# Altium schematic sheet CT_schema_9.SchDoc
size 277 x 170 mm
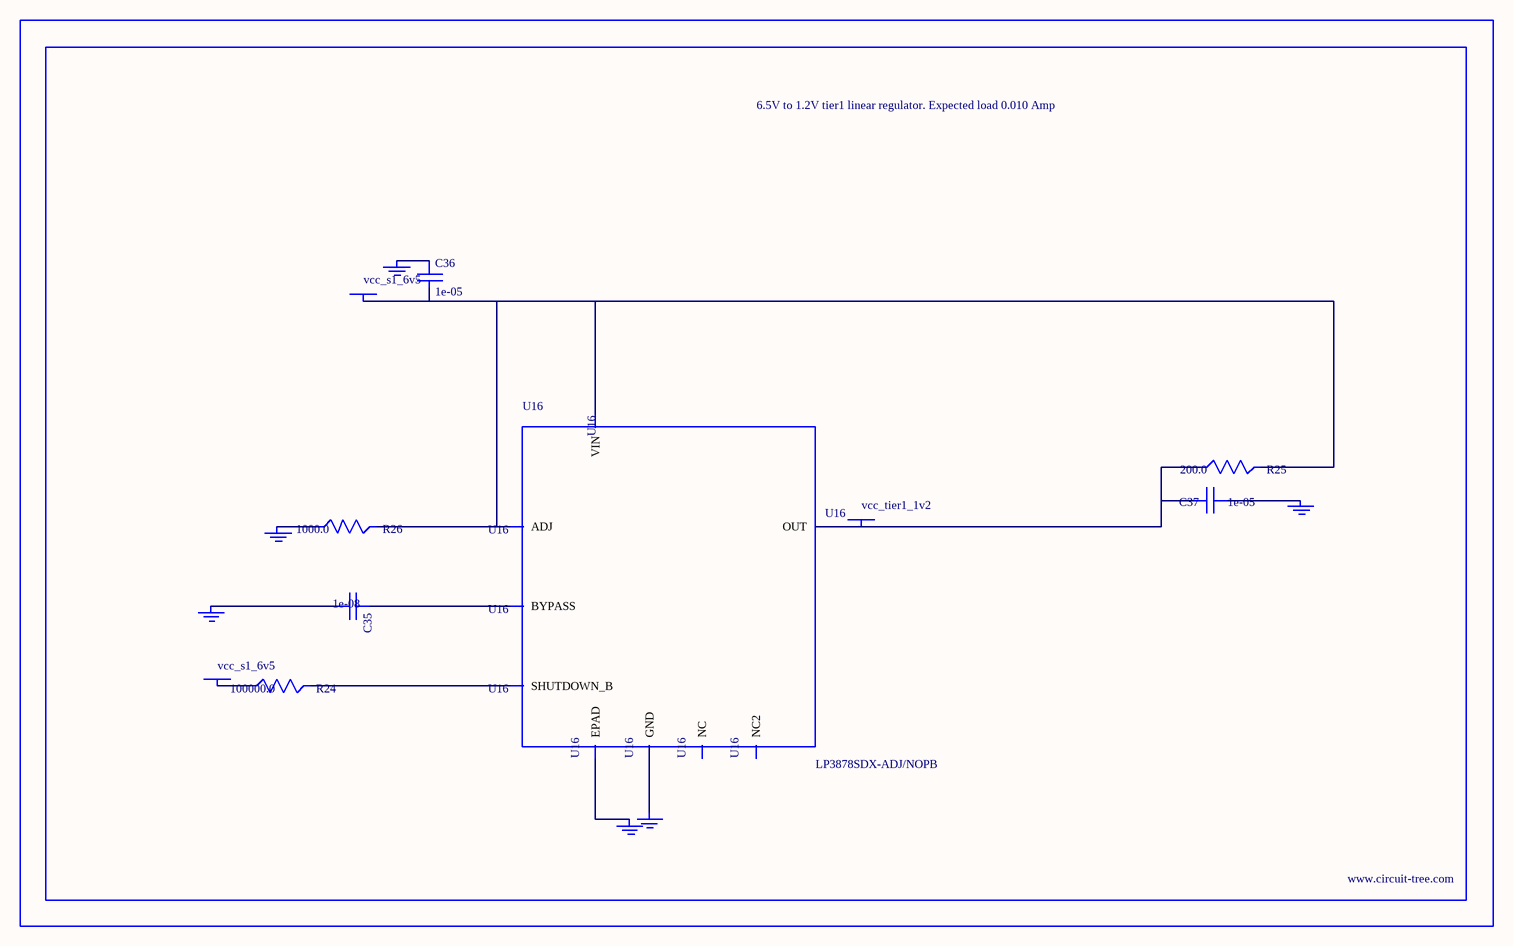
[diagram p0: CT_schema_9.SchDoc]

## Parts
BORDER8  (no value)
C35  1e-08  [C0402]
C36  1e-05  [C1206]
C37  1e-05  [C0805]
GND_INSTANCE_8_0  (no value)
GND_INSTANCE_8_1  (no value)
GND_INSTANCE_8_2  (no value)
GND_INSTANCE_8_3  (no value)
GND_INSTANCE_8_4  (no value)
GND_INSTANCE_8_5  (no value)
POWER_INSTANCE_8_0  vcc_s1_6v5
POWER_INSTANCE_8_1  vcc_s1_6v5
POWER_INSTANCE_8_2  vcc_tier1_1v2
R24  100000.0  [R0603]
R25  200.0  [R0603]
R26  1000.0  [R0603]
U16  LP3878SDX-ADJ/NOPB  [WSON-8]

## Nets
NetC35_1: C35.1 U16.1(BYPASS)
NetC35_2: C35.2 GND_INSTANCE_8_0.0(GND)
NetC36_1: C36.1 GND_INSTANCE_8_1.0(GND)
NetC36_2: C36.2 POWER_INSTANCE_8_0.0(PWR) R25.2 R26.2 U16.4(VIN) U16.6(ADJ)
NetC37_1: C37.1 GND_INSTANCE_8_2.0(GND)
NetC37_2: C37.2 POWER_INSTANCE_8_2.0(PWR) R25.1 U16.5(OUT)
NetGND_INSTANCE_8_3_0: GND_INSTANCE_8_3.0(GND) R26.1
NetGND_INSTANCE_8_4_0: GND_INSTANCE_8_4.0(GND) U16.PAD(EPAD)
NetGND_INSTANCE_8_5_0: GND_INSTANCE_8_5.0(GND) U16.3(GND)
NetPOWER_INSTANCE_8_1_0: POWER_INSTANCE_8_1.0(PWR) R24.1
NetR24_2: R24.2 U16.8(SHUTDOWN_B)

Not connected (* = marked no-connect by the designer): U16 2(NC) 7(NC2)

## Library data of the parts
BORDER8 = BORDER_PAGE8
C35 = C0402C103K3RAC
C36 = C1206C106K3RACTU
C37 = GRM219R60J106ME19D
GND_INSTANCE_8_0-GND_INSTANCE_8_5 = GND
POWER_INSTANCE_8_0-POWER_INSTANCE_8_2 = PWR
R24 = RC0603JR-07100KL
R25 = RC0603JR-07200RL
R26 = RC0603JR-071KL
